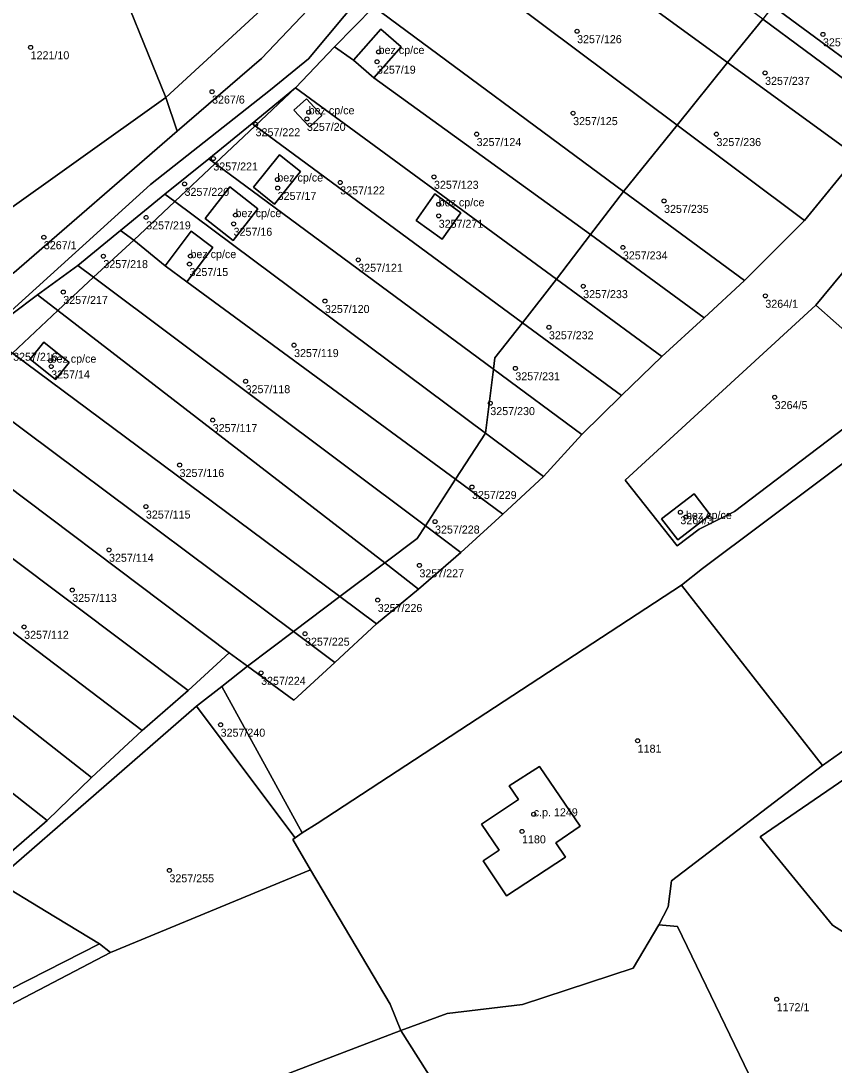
# Model space of a CAD drawing. Extents: x -878211 to -870363, y -1058464 to -1052522.
# Drawn here: x -875693.5 to -875591.8, y -1056468.6 to -1056338.1 of the extents above; entities that cross this region are included whole.
import ezdxf

# ---------------------------------------------------------------- set-up
doc = ezdxf.new("R2010")
doc.units = 0
for name, color, linetype in [('Definiční body', 7, 'Continuous'), ('Polygon budovy', 7, 'Continuous'), ('Polygon parcely', 7, 'Continuous')]:
    doc.layers.add(name, color=color, linetype=linetype)

msp = doc.modelspace()

# ---------------------------------------------------------------- linework, layer by layer
at = {"layer": 'Definiční body'}
for centre in [(-875623.97, -1056339.36994), (-875593.24, -1056339.75994), (-875692.28, -1056341.37994), (-875648.78, -1056341.95994), (-875648.98, -1056343.17994), (-875600.47, -1056344.57994), (-875669.6, -1056346.91994), (-875657.74, -1056350.32994), (-875657.52, -1056349.49994), (-875624.47, -1056349.60994), (-875664.16, -1056350.99994), (-875636.53, -1056352.22994), (-875606.55, -1056352.22994), (-875669.44, -1056355.27994), (-875673.04, -1056358.44994), (-875661.44, -1056357.89994), (-875653.58, -1056358.26994), (-875641.86, -1056357.56994), (-875661.4, -1056358.95994), (-875641.27, -1056360.99994), (-875613.1, -1056360.57994), (-875666.67, -1056362.34994), (-875677.84, -1056362.63994), (-875666.91, -1056363.43994), (-875641.27, -1056362.43994), (-875690.63, -1056365.11994), (-875683.19, -1056367.47994), (-875672.3, -1056367.46994), (-875618.25, -1056366.38994), (-875672.42, -1056368.46994), (-875651.33, -1056367.93994), (-875623.21, -1056371.22994), (-875688.2, -1056371.95994), (-875600.44, -1056372.43994), (-875655.49, -1056373.08994), (-875627.49, -1056376.36994), (-875659.35, -1056378.59994), (-875689.79, -1056380.53994), (-875689.71, -1056381.26994), (-875631.69, -1056381.49994), (-875665.41, -1056383.10994), (-875634.82, -1056385.84994), (-875599.27, -1056385.09994), (-875669.52, -1056387.96994), (-875673.66, -1056393.57994), (-875637.11, -1056396.32994), (-875677.87, -1056398.77994), (-875611.06, -1056399.48994), (-875610.36, -1056400.07994), (-875641.73, -1056400.64994), (-875682.48, -1056404.17994), (-875643.68, -1056406.11994), (-875687.08, -1056409.19994), (-875648.89, -1056410.45994), (-875693.09, -1056413.80994), (-875657.98, -1056414.66994), (-875663.47, -1056419.55994), (-875668.53, -1056426.03994), (-875616.4, -1056428.03994), (-875629.39, -1056437.22994), (-875630.85, -1056439.36994), (-875674.93, -1056444.23994), (-875599.02, -1056460.34994)]:
    msp.add_circle(centre, 0.25, dxfattribs=at)
at = {"layer": 'Polygon budovy'}
for points in [[(-875648.52, -1056339.09), (-875651.93, -1056342.98), (-875649.39, -1056345.2), (-875645.98, -1056341.31)], [(-875655.86, -1056349.9), (-875657.78, -1056347.81), (-875659.36, -1056349.22), (-875657.42, -1056351.33)], [(-875664.42, -1056358.87), (-875661.8, -1056360.96), (-875658.55, -1056356.91), (-875661.17, -1056354.81)], [(-875670.48, -1056362.79), (-875666.97, -1056365.53), (-875663.87, -1056361.55), (-875667.38, -1056358.81)], [(-875641.76, -1056359.7), (-875644.09, -1056363.01), (-875640.83, -1056365.36), (-875638.51, -1056362.07)], [(-875675.46, -1056368.68), (-875672.76, -1056370.69), (-875669.52, -1056366.4), (-875672.23, -1056364.35)], [(-875692.34, -1056380.33), (-875689.17, -1056382.88), (-875687.46, -1056380.77), (-875690.61, -1056378.23)], [(-875613.4, -1056400.29), (-875611.39, -1056402.91), (-875607.34, -1056399.82), (-875609.34, -1056397.2)], [(-875631.3, -1056435.38), (-875635.9, -1056438.46), (-875633.71, -1056441.73), (-875635.7, -1056443.06), (-875632.79, -1056447.41), (-875625.41, -1056442.59), (-875626.63, -1056440.79), (-875623.6, -1056438.73), (-875628.65, -1056431.25), (-875632.45, -1056433.67)]]:
    msp.add_lwpolyline(points, close=True, dxfattribs=at)
at = {"layer": 'Polygon parcely'}
for points in [[(-875642.54, -1056321.47), (-875642.63, -1056314.95), (-875651.97, -1056298.54), (-875650.62, -1056304.44), (-875646.62, -1056318.65), (-875647.82, -1056322.26), (-875646.14, -1056324.55), (-875663.43, -1056342.76), (-875673.95, -1056351.87), (-875694.33, -1056369.52), (-875703.32, -1056374.74), (-875703.43, -1056377.18), (-875695.25, -1056372.67), (-875703.53, -1056381.51), (-875697.87, -1056377.14), (-875677.29, -1056358.5), (-875662.3, -1056346.67), (-875657.54, -1056342.8), (-875646.31, -1056329.33)], [(-875675.36, -1056347.63), (-875647.82, -1056322.26), (-875646.62, -1056318.65), (-875650.62, -1056304.44), (-875653.97, -1056301.14), (-875687.42, -1056318.06), (-875686.75, -1056319.66), (-875682.59, -1056329.88)], [(-875630.56, -1056323.77), (-875631.34, -1056323.15), (-875632.51, -1056322.22), (-875633.26, -1056322.84), (-875605.16, -1056343.28), (-875600.77, -1056337.84), (-875627.63, -1056318.01), (-875628.6, -1056318.82), (-875628.17, -1056319.16), (-875627.39, -1056319.78)], [(-875696.95, -1056363.01), (-875675.36, -1056347.63), (-875682.59, -1056329.88), (-875686.86, -1056319.7), (-875689.62, -1056320.79), (-875703.74, -1056326.61), (-875699.54, -1056336.78), (-875704.48, -1056338.69)], [(-875647.82, -1056322.26), (-875675.36, -1056347.63), (-875673.95, -1056351.87), (-875663.43, -1056342.76), (-875646.14, -1056324.55)], [(-875611.46, -1056351.09), (-875605.16, -1056343.28), (-875633.26, -1056322.84), (-875640.83, -1056329.12)], [(-875577.49, -1056339.39), (-875592.83, -1056327.79), (-875599.51, -1056336.25), (-875583.55, -1056347.97)], [(-875640.83, -1056329.12), (-875642.54, -1056328.24), (-875649.39, -1056336.33), (-875618.16, -1056359.39), (-875611.46, -1056351.09)], [(-875618.16, -1056359.39), (-875649.39, -1056336.33), (-875654.29, -1056341.32), (-875651.93, -1056342.98), (-875648.52, -1056339.09), (-875645.98, -1056341.31), (-875649.39, -1056345.2), (-875622.28, -1056364.78)], [(-875600.77, -1056337.84), (-875605.16, -1056343.28), (-875589.02, -1056355.02), (-875584.87, -1056349.59)], [(-875651.93, -1056342.98), (-875649.39, -1056345.2), (-875645.98, -1056341.31), (-875648.52, -1056339.09)], [(-875654.29, -1056341.32), (-875659.19, -1056346.43), (-875626.55, -1056370.35), (-875622.28, -1056364.78), (-875649.39, -1056345.2), (-875651.93, -1056342.98)], [(-875589.02, -1056355.02), (-875605.16, -1056343.28), (-875611.46, -1056351.09), (-875595.53, -1056363)], [(-875664.21, -1056351.17), (-875659.19, -1056346.43), (-875664.6, -1056350.88)], [(-875664.21, -1056351.17), (-875630.79, -1056375.79), (-875626.55, -1056370.35), (-875659.19, -1056346.43)], [(-875702.92, -1056366.62), (-875703.32, -1056374.74), (-875694.33, -1056369.52), (-875673.95, -1056351.87), (-875675.36, -1056347.63), (-875696.95, -1056363.01), (-875699.5, -1056364.57), (-875702.08, -1056366.29)], [(-875657.42, -1056351.33), (-875655.86, -1056349.9), (-875657.78, -1056347.81), (-875659.36, -1056349.22)], [(-875657.42, -1056351.33), (-875659.36, -1056349.22), (-875657.78, -1056347.81), (-875655.86, -1056349.9)], [(-875664.6, -1056350.88), (-875670, -1056355.32), (-875669.22, -1056355.9), (-875664.21, -1056351.17)], [(-875634.42, -1056381.61), (-875634.24, -1056380.2), (-875630.79, -1056375.79), (-875664.21, -1056351.17), (-875669.22, -1056355.9)], [(-875611.46, -1056351.09), (-875618.16, -1056359.39), (-875603.06, -1056370.53), (-875595.53, -1056363)], [(-875669.22, -1056355.9), (-875670, -1056355.32), (-875675.52, -1056359.72), (-875674.27, -1056360.66)], [(-875658.55, -1056356.91), (-875661.17, -1056354.81), (-875664.42, -1056358.87), (-875661.8, -1056360.96)], [(-875658.55, -1056356.91), (-875661.8, -1056360.96), (-875664.42, -1056358.87), (-875661.17, -1056354.81)], [(-875583.95, -1056382.58), (-875583.31, -1056383.43), (-875604.31, -1056399.4), (-875608.7, -1056401.61), (-875611.46, -1056403.66), (-875617.97, -1056395.49), (-875594.13, -1056373.59), (-875578.31, -1056354.5), (-875565.22, -1056366.84)], [(-875583.95, -1056382.58), (-875565.22, -1056366.84), (-875578.31, -1056354.5), (-875594.13, -1056373.59)], [(-875635.43, -1056389.61), (-875634.42, -1056381.61), (-875669.22, -1056355.9), (-875674.27, -1056360.66)], [(-875663.87, -1056361.55), (-875667.38, -1056358.81), (-875670.48, -1056362.79), (-875666.97, -1056365.53)], [(-875663.87, -1056361.55), (-875666.97, -1056365.53), (-875670.48, -1056362.79), (-875667.38, -1056358.81)], [(-875603.06, -1056370.53), (-875618.16, -1056359.39), (-875622.28, -1056364.78), (-875608.1, -1056375.17)], [(-875675.52, -1056359.72), (-875681.06, -1056364.25), (-875679.39, -1056365.49), (-875674.27, -1056360.66)], [(-875639.15, -1056395.35), (-875635.43, -1056389.61), (-875674.27, -1056360.66), (-875679.39, -1056365.49), (-875675.46, -1056368.68), (-875672.23, -1056364.35), (-875669.52, -1056366.4), (-875672.76, -1056370.69)], [(-875638.51, -1056362.07), (-875640.83, -1056365.36), (-875644.09, -1056363.01), (-875641.76, -1056359.7)], [(-875638.51, -1056362.07), (-875641.76, -1056359.7), (-875644.09, -1056363.01), (-875640.83, -1056365.36)], [(-875679.39, -1056365.49), (-875681.06, -1056364.25), (-875686.4, -1056368.63), (-875684.44, -1056370.1)], [(-875675.46, -1056368.68), (-875672.76, -1056370.69), (-875669.52, -1056366.4), (-875672.23, -1056364.35)], [(-875679.39, -1056365.49), (-875684.44, -1056370.1), (-875642.93, -1056401.19), (-875639.15, -1056395.35), (-875672.76, -1056370.69), (-875675.46, -1056368.68)], [(-875622.28, -1056364.78), (-875626.55, -1056370.35), (-875613.39, -1056380), (-875608.1, -1056375.17)], [(-875684.44, -1056370.1), (-875686.4, -1056368.63), (-875691.41, -1056372.29), (-875688.86, -1056374.26)], [(-875642.93, -1056401.19), (-875684.44, -1056370.1), (-875688.86, -1056374.26), (-875648.02, -1056405.82), (-875643.96, -1056402.78)], [(-875613.39, -1056380), (-875626.55, -1056370.35), (-875630.79, -1056375.79), (-875618.41, -1056384.91)], [(-875691.41, -1056372.29), (-875697.87, -1056377.14), (-875694.55, -1056379.61), (-875688.86, -1056374.26)], [(-875594.13, -1056373.59), (-875617.97, -1056395.49), (-875611.46, -1056403.66), (-875608.7, -1056401.61), (-875604.31, -1056399.4), (-875583.31, -1056383.43), (-875583.95, -1056382.58)], [(-875553.41, -1056410.58), (-875553.97, -1056407.84), (-875555.06, -1056404.79), (-875552.12, -1056400.34), (-875550.72, -1056388.46), (-875555.26, -1056383.73), (-875565.35, -1056373.86), (-875570, -1056377.85), (-875608.29, -1056406.53), (-875610.91, -1056408.61), (-875593.3, -1056431.12), (-875586.9, -1056426.64), (-875575.1, -1056419.93), (-875574.64, -1056421.91), (-875574.07, -1056424.31), (-875572.18, -1056423.23)], [(-875688.86, -1056374.26), (-875694.55, -1056379.61), (-875653.61, -1056410.02), (-875648.02, -1056405.82)], [(-875630.79, -1056375.79), (-875634.24, -1056380.2), (-875634.42, -1056381.61), (-875623.36, -1056389.78), (-875618.41, -1056384.91)], [(-875687.46, -1056380.77), (-875690.61, -1056378.23), (-875692.34, -1056380.33), (-875689.17, -1056382.88)], [(-875687.46, -1056380.77), (-875689.17, -1056382.88), (-875692.34, -1056380.33), (-875690.61, -1056378.23)], [(-875653.61, -1056410.02), (-875694.55, -1056379.61), (-875699.65, -1056384.4), (-875659.44, -1056414.39)], [(-875623.36, -1056389.78), (-875634.42, -1056381.61), (-875635.43, -1056389.61), (-875628.16, -1056395.03)], [(-875703.79, -1056389.6), (-875703.86, -1056389.64), (-875667.46, -1056417.05), (-875665.19, -1056418.71), (-875659.44, -1056414.39), (-875699.65, -1056384.4), (-875700.57, -1056385.27), (-875698.03, -1056387.16), (-875701, -1056391.2), (-875703.56, -1056389.29)], [(-875708.4, -1056394.41), (-875709.86, -1056393.35), (-875710.17, -1056393.54), (-875672.6, -1056421.76), (-875667.46, -1056417.05), (-875703.86, -1056389.64), (-875706.12, -1056391.04), (-875705.99, -1056391.13)], [(-875635.43, -1056389.61), (-875639.15, -1056395.35), (-875633.27, -1056399.71), (-875628.16, -1056395.03)], [(-875712.35, -1056391.91), (-875718.42, -1056396.35), (-875678.32, -1056426.74), (-875672.6, -1056421.76), (-875710.17, -1056393.54)], [(-875633.27, -1056399.71), (-875639.15, -1056395.35), (-875642.93, -1056401.19), (-875638.51, -1056404.5)], [(-875684.66, -1056432.63), (-875678.32, -1056426.74), (-875718.42, -1056396.35), (-875725.35, -1056400.72)], [(-875611.39, -1056402.91), (-875607.34, -1056399.82), (-875609.34, -1056397.2), (-875613.4, -1056400.29)], [(-875611.39, -1056402.91), (-875613.4, -1056400.29), (-875609.34, -1056397.2), (-875607.34, -1056399.82)], [(-875690.22, -1056437.99), (-875684.66, -1056432.63), (-875725.35, -1056400.72), (-875732.12, -1056404.99)], [(-875638.51, -1056404.5), (-875642.93, -1056401.19), (-875643.96, -1056402.78), (-875648.02, -1056405.82), (-875643.79, -1056409.09)], [(-875732.12, -1056404.99), (-875739.21, -1056409.46), (-875696.35, -1056443.28), (-875690.22, -1056437.99)], [(-875648.02, -1056405.82), (-875653.61, -1056410.02), (-875649.03, -1056413.43), (-875643.79, -1056409.09)], [(-875610.91, -1056408.61), (-875656.45, -1056438.39), (-875658.35, -1056439.56), (-875659.22, -1056440.19), (-875659.5, -1056440.39), (-875657.28, -1056444.15), (-875647.35, -1056460.95), (-875646, -1056464.24), (-875640.22, -1056462.14), (-875630.79, -1056460.99), (-875616.97, -1056456.47), (-875613.76, -1056451.04), (-875612.59, -1056448.8), (-875612.19, -1056445.54), (-875593.3, -1056431.12)], [(-875649.03, -1056413.43), (-875653.61, -1056410.02), (-875659.44, -1056414.39), (-875654.24, -1056418.27)], [(-875659.44, -1056414.39), (-875665.19, -1056418.71), (-875659.37, -1056422.97), (-875654.24, -1056418.27)], [(-875568.53, -1056461.56), (-875558.91, -1056456.14), (-875559.82, -1056453.69), (-875574.31, -1056455.44), (-875583.46, -1056456.55), (-875592.06, -1056451.07), (-875601.1, -1056440.06), (-875574.64, -1056421.91), (-875575.1, -1056419.93), (-875586.9, -1056426.64), (-875593.3, -1056431.12), (-875612.19, -1056445.54), (-875612.59, -1056448.8), (-875613.76, -1056451.04), (-875611.4, -1056451.27), (-875600.7, -1056473.41), (-875598.32, -1056478.33)], [(-875663.89, -1056433.96), (-875659.22, -1056440.19), (-875658.35, -1056439.56), (-875662.35, -1056432.27), (-875668.4, -1056421.24), (-875671.55, -1056423.73)], [(-875564.26, -1056442.37), (-875566.6, -1056443.25), (-875573.54, -1056428.13), (-875574.07, -1056424.31), (-875574.64, -1056421.91), (-875601.1, -1056440.06), (-875592.06, -1056451.07), (-875583.46, -1056456.55), (-875563.51, -1056444.15)], [(-875659.5, -1056440.39), (-875659.22, -1056440.19), (-875663.89, -1056433.96), (-875671.55, -1056423.73), (-875696.67, -1056445.53), (-875690.35, -1056449.36), (-875683.67, -1056453.41), (-875682.29, -1056454.52), (-875657.28, -1056444.15)], [(-875625.41, -1056442.59), (-875626.63, -1056440.79), (-875623.6, -1056438.73), (-875628.65, -1056431.25), (-875632.45, -1056433.67), (-875631.3, -1056435.38), (-875635.9, -1056438.46), (-875633.71, -1056441.73), (-875635.7, -1056443.06), (-875632.79, -1056447.41)], [(-875625.41, -1056442.59), (-875632.79, -1056447.41), (-875635.7, -1056443.06), (-875633.71, -1056441.73), (-875635.9, -1056438.46), (-875631.3, -1056435.38), (-875632.45, -1056433.67), (-875628.65, -1056431.25), (-875623.6, -1056438.73), (-875626.63, -1056440.79)], [(-875616.97, -1056456.47), (-875630.79, -1056460.99), (-875640.22, -1056462.14), (-875646, -1056464.24), (-875638.73, -1056475.75), (-875640.09, -1056476.7), (-875637.61, -1056480.81), (-875636.07, -1056479.95), (-875628.33, -1056492.21), (-875600.7, -1056473.41), (-875611.4, -1056451.27), (-875613.76, -1056451.04)], [(-875779.94, -1056503.64), (-875719.03, -1056473.69), (-875682.29, -1056454.52), (-875683.67, -1056453.41), (-875717, -1056470.38), (-875752.35, -1056487.54), (-875781.56, -1056501.24), (-875819.27, -1056524.13)], [(-875628.33, -1056492.21), (-875636.07, -1056479.95), (-875637.61, -1056480.81), (-875640.09, -1056476.7), (-875638.73, -1056475.75), (-875646, -1056464.24), (-875666.38, -1056472.05), (-875645.67, -1056505.48), (-875631.83, -1056494.17), (-875628.26, -1056495.05), (-875627.01, -1056494.3)]]:
    msp.add_lwpolyline(points, close=True, dxfattribs=at)
for points in [[(-875646.31, -1056329.33), (-875657.54, -1056342.8), (-875662.3, -1056346.67), (-875677.29, -1056358.5), (-875697.87, -1056377.14), (-875691.41, -1056372.29), (-875686.4, -1056368.63), (-875681.06, -1056364.25), (-875675.52, -1056359.72), (-875670, -1056355.32), (-875664.6, -1056350.88), (-875659.19, -1056346.43), (-875654.29, -1056341.32), (-875649.39, -1056336.33)], [(-875583.55, -1056347.97), (-875599.51, -1056336.25), (-875600.77, -1056337.84), (-875584.87, -1056349.59)], [(-875589.02, -1056355.02), (-875595.53, -1056363), (-875603.06, -1056370.53), (-875608.1, -1056375.17), (-875613.39, -1056380), (-875618.41, -1056384.91), (-875623.36, -1056389.78), (-875628.16, -1056395.03), (-875633.27, -1056399.71), (-875638.51, -1056404.5), (-875643.79, -1056409.09), (-875649.03, -1056413.43), (-875654.24, -1056418.27), (-875659.37, -1056422.97), (-875665.19, -1056418.71), (-875668.4, -1056421.24), (-875662.35, -1056432.27), (-875658.35, -1056439.56), (-875656.45, -1056438.39), (-875610.91, -1056408.61), (-875608.29, -1056406.53), (-875570, -1056377.85)], [(-875781.56, -1056501.24), (-875752.35, -1056487.54), (-875717, -1056470.38), (-875683.67, -1056453.41), (-875690.35, -1056449.36), (-875696.67, -1056445.53), (-875671.55, -1056423.73), (-875668.4, -1056421.24), (-875665.19, -1056418.71), (-875667.46, -1056417.05), (-875672.6, -1056421.76), (-875678.32, -1056426.74), (-875684.66, -1056432.63), (-875690.22, -1056437.99), (-875696.35, -1056443.28), (-875701.98, -1056448.55), (-875707.54, -1056453.71), (-875713.43, -1056459), (-875719.97, -1056462.99), (-875726.86, -1056467.19), (-875734.26, -1056470.83), (-875741.5, -1056474.31), (-875748.75, -1056477.85), (-875756.09, -1056481.43)], [(-875759.48, -1056564.16), (-875723.29, -1056542.13), (-875716.38, -1056537.2), (-875717.03, -1056535.81), (-875729.78, -1056508.48), (-875719.88, -1056502.91), (-875714.95, -1056500.14), (-875700.83, -1056492.19), (-875688.06, -1056485.53), (-875687.4, -1056483.33), (-875667.88, -1056472.85), (-875666.38, -1056472.05), (-875646, -1056464.24), (-875647.35, -1056460.95), (-875657.28, -1056444.15), (-875682.29, -1056454.52), (-875719.03, -1056473.69), (-875779.94, -1056503.64)]]:
    msp.add_lwpolyline(points, dxfattribs=at)

# ---------------------------------------------------------------- texts
at = {"layer": 'Definiční body'}
for s, p in [('3257/126', (-875623.97, -1056340.859)), ('bez cp/ce', (-875648.78, -1056342.21)), ('3257/238', (-875593.24, -1056341.249)), ('1221/10', (-875692.28, -1056342.869)), ('3257/19', (-875648.98, -1056344.669)), ('3257/237', (-875600.47, -1056346.069)), ('3267/6', (-875669.6, -1056348.409)), ('bez cp/ce', (-875657.52, -1056349.75)), ('3257/125', (-875624.47, -1056351.099)), ('3257/222', (-875664.16, -1056352.489)), ('3257/20', (-875657.74, -1056351.819)), ('3257/124', (-875636.53, -1056353.719)), ('3257/236', (-875606.55, -1056353.719)), ('3257/221', (-875669.44, -1056356.769)), ('bez cp/ce', (-875661.44, -1056358.149)), ('3257/123', (-875641.86, -1056359.059)), ('3257/220', (-875673.04, -1056359.939)), ('3257/17', (-875661.4, -1056360.449)), ('3257/122', (-875653.58, -1056359.759)), ('bez cp/ce', (-875641.27, -1056361.25)), ('bez cp/ce', (-875666.67, -1056362.6)), ('3257/235', (-875613.1, -1056362.069)), ('3257/219', (-875677.84, -1056364.129)), ('3257/271', (-875641.27, -1056363.929)), ('3257/16', (-875666.91, -1056364.929)), ('3267/1', (-875690.63, -1056366.609)), ('bez cp/ce', (-875672.3, -1056367.72)), ('3257/234', (-875618.25, -1056367.879)), ('3257/218', (-875683.19, -1056368.969)), ('3257/121', (-875651.33, -1056369.429)), ('3257/15', (-875672.42, -1056369.959)), ('3257/217', (-875688.2, -1056373.449)), ('3257/233', (-875623.21, -1056372.719)), ('3257/120', (-875655.49, -1056374.579)), ('3264/1', (-875600.44, -1056373.929)), ('3257/232', (-875627.49, -1056377.859)), ('3257/119', (-875659.35, -1056380.089)), ('3257/216', (-875694.47, -1056380.549)), ('bez cp/ce', (-875689.79, -1056380.79)), ('3257/14', (-875689.71, -1056382.759)), ('3257/231', (-875631.69, -1056382.989)), ('3257/118', (-875665.41, -1056384.599)), ('3264/5', (-875599.27, -1056386.589)), ('3257/230', (-875634.82, -1056387.339)), ('3257/117', (-875669.52, -1056389.459)), ('3257/116', (-875673.66, -1056395.069)), ('3257/229', (-875637.11, -1056397.819)), ('3257/115', (-875677.87, -1056400.269)), ('3264/3', (-875611.06, -1056400.979)), ('bez cp/ce', (-875610.36, -1056400.33)), ('3257/228', (-875641.73, -1056402.139)), ('3257/114', (-875682.48, -1056405.669)), ('3257/227', (-875643.68, -1056407.609)), ('3257/113', (-875687.08, -1056410.689)), ('3257/226', (-875648.89, -1056411.949)), ('3257/112', (-875693.09, -1056415.299)), ('3257/225', (-875657.98, -1056416.159)), ('3257/224', (-875663.47, -1056421.049)), ('3257/240', (-875668.53, -1056427.529)), ('1181', (-875616.4, -1056429.529)), ('c.p. 1249', (-875629.39, -1056437.48)), ('1180', (-875630.85, -1056440.859)), ('3257/255', (-875674.93, -1056445.729)), ('1172/1', (-875599.02, -1056461.839))]:
    msp.add_text(s, height=0.999996, dxfattribs=at).set_placement(p)

doc.saveas('drawing.dxf')
